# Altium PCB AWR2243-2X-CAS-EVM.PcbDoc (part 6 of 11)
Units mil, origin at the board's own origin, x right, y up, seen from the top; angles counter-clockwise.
Board outline 5118.11 x 3937.01 mil, 8 copper layers (Layer 1 - Top Layer, Layer 2 - GND, Layer 3 - Signal (Sensitive), Layer 4 - GND / Signal, Layer 5 - Signal, Layer 6 - PWR / Signal, Layer 7 - GND, Layer 8 - Bottom Layer), stack 54.8 mil thick; 629 components, 407 nets, 2243 pads, 3950 vias.
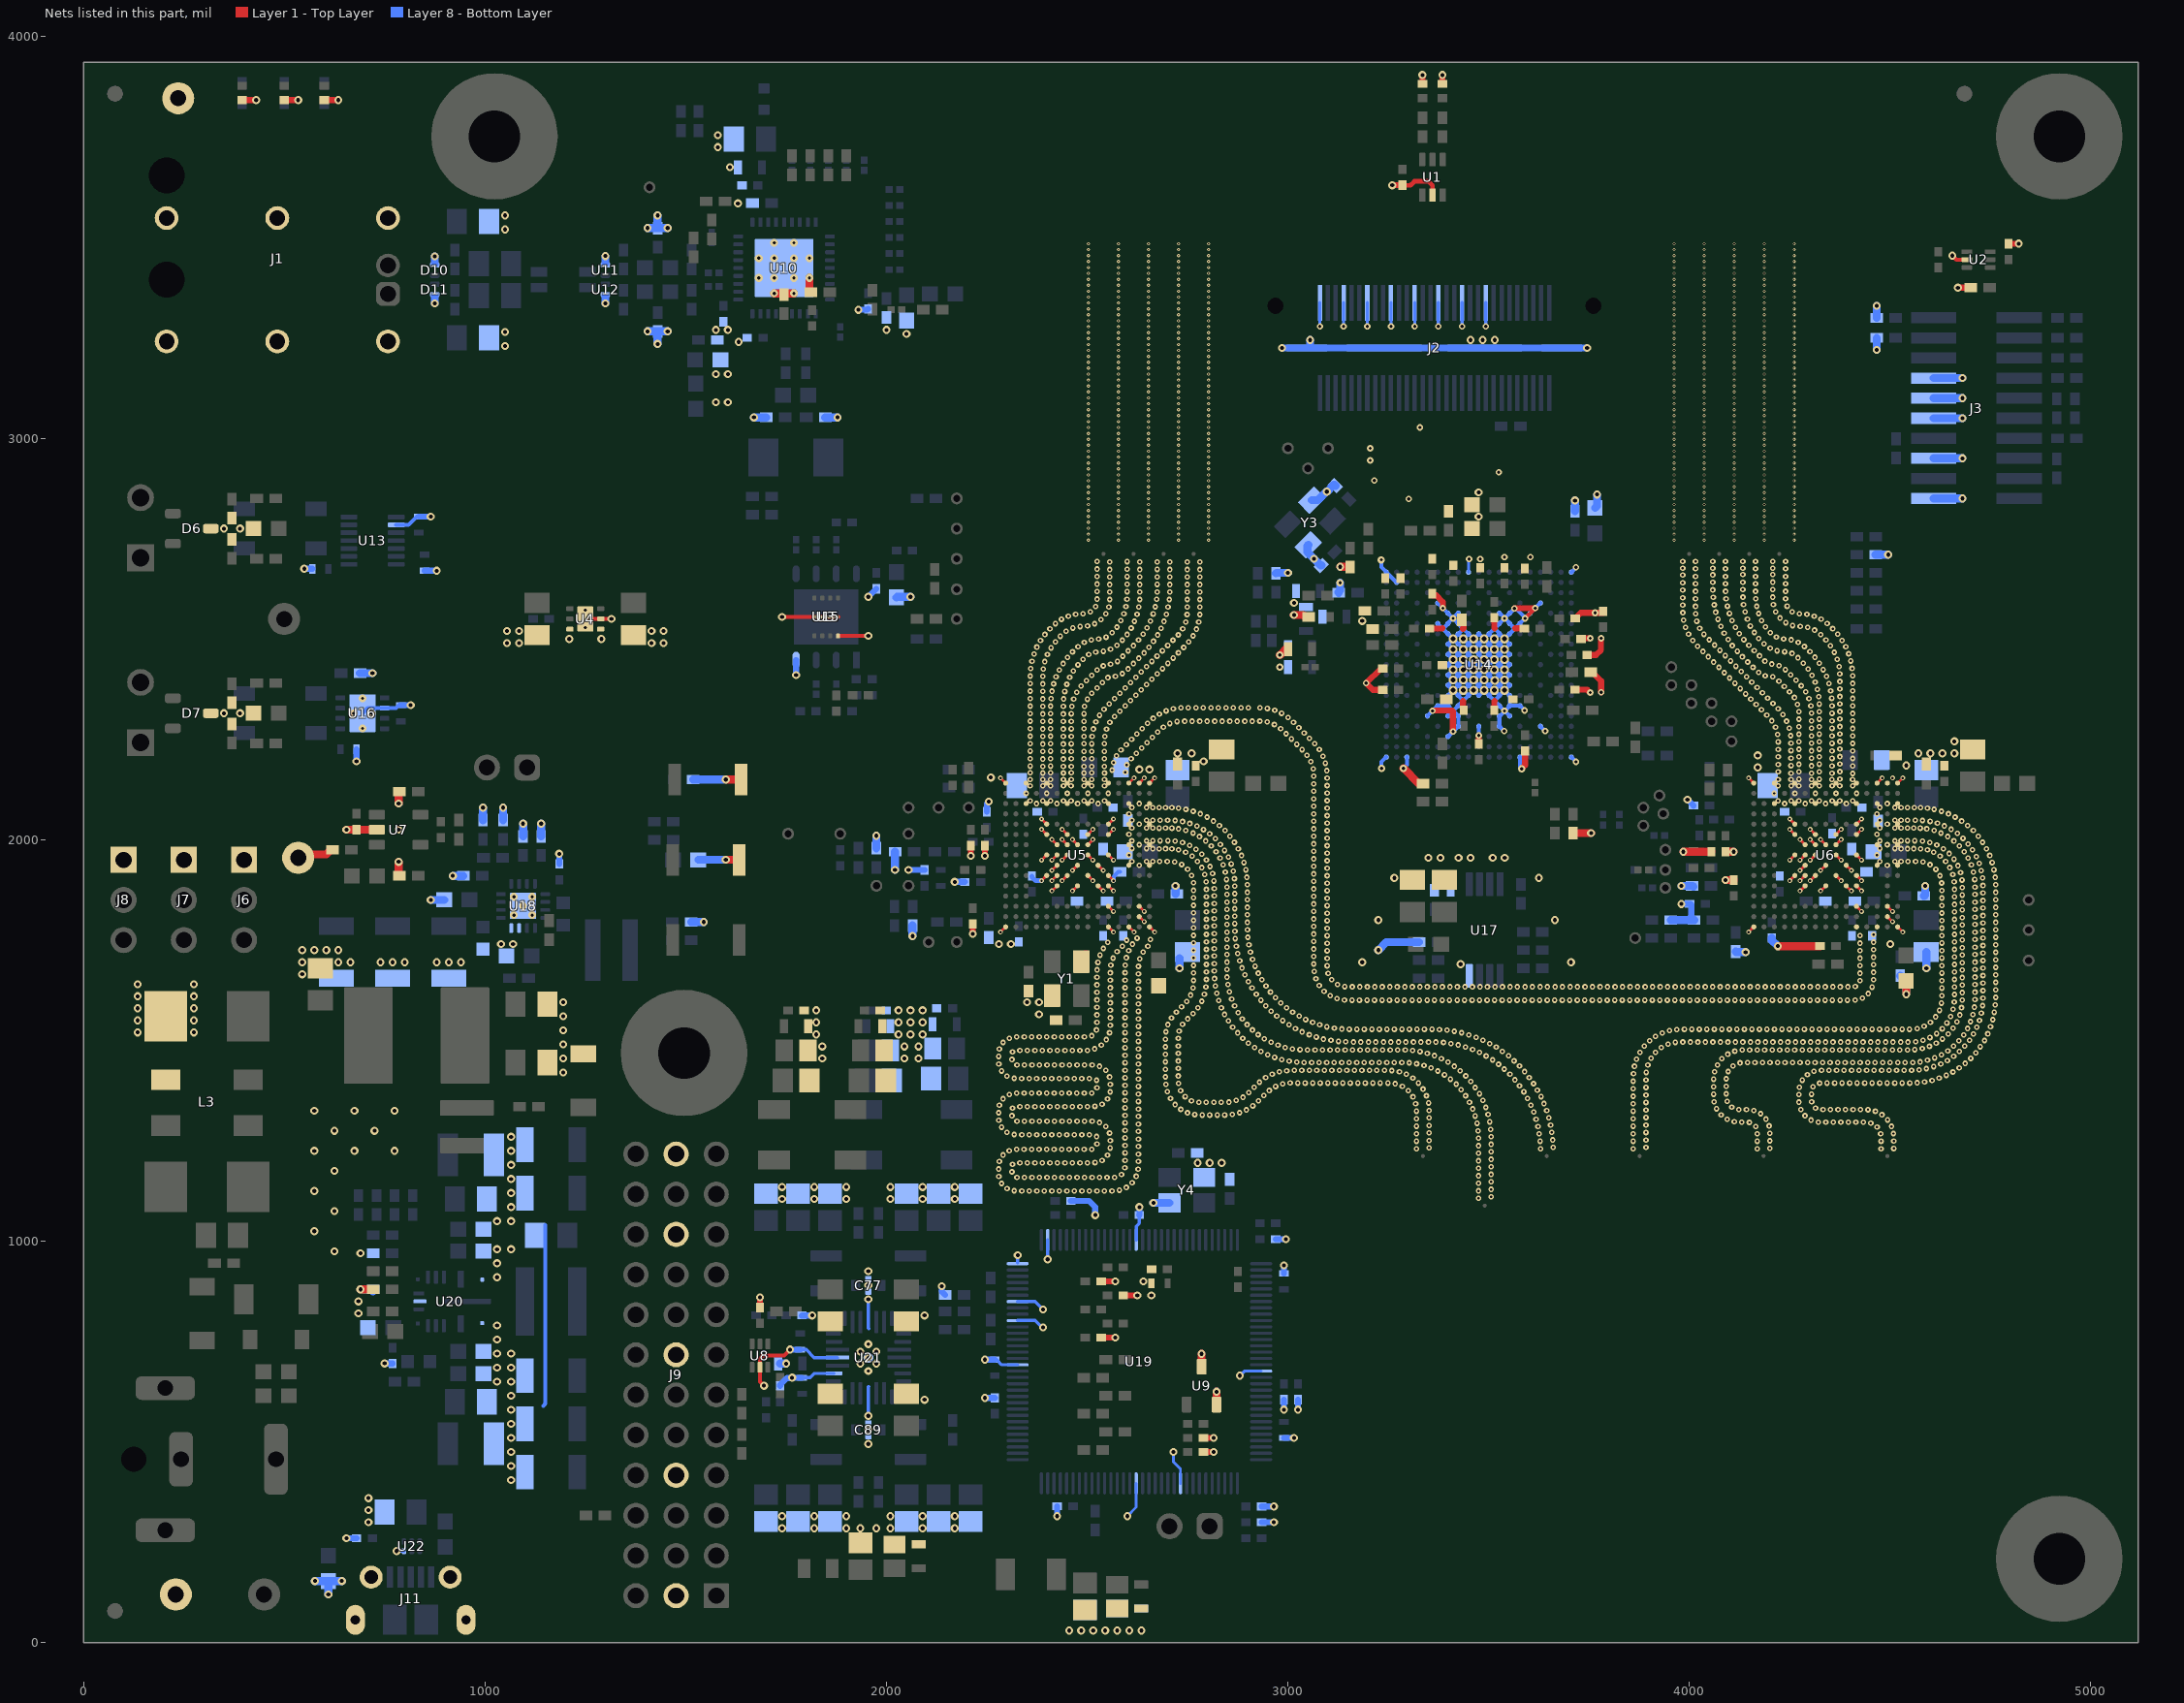
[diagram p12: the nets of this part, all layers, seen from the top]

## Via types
v1: diameter 13.78, hole 5.91, Layer 1 - Top Layer to Layer 2 - GND, tented top, 2104 vias
v2: diameter 20, hole 10, Layer 1 - Top Layer to Layer 8 - Bottom Layer, tented both sides, 831 vias
v3: diameter 7.87, hole 3.94, Layer 1 - Top Layer to Layer 2 - GND, tented top, 510 vias
v4: diameter 12, hole 6, Layer 1 - Top Layer to Layer 8 - Bottom Layer, tented both sides, 176 vias
v5: diameter 16, hole 8, Layer 1 - Top Layer to Layer 8 - Bottom Layer, tented both sides, 138 vias
v6: diameter 13.78, hole 5.91, Layer 1 - Top Layer to Layer 2 - GND, tented both sides, 88 vias
v7: diameter 18, hole 8, Layer 1 - Top Layer to Layer 8 - Bottom Layer, tented both sides, 41 vias
v8: diameter 22, hole 12, Layer 1 - Top Layer to Layer 8 - Bottom Layer, tented both sides, 36 vias
v9: diameter 19.68, hole 7.87, Layer 1 - Top Layer to Layer 8 - Bottom Layer, tented both sides, 26 vias

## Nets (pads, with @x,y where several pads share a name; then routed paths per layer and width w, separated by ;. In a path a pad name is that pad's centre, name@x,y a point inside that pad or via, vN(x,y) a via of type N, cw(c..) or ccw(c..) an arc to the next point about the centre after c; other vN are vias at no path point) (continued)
GND: C1.1 C2.1 C3.2 C4.1 C5.1 C6.1 C7.2 C8.1 C9.1 C10.1 C11.1 C12.1 C13.1 C14.1 C15.1 C16.2 C17.2 C18.2 C19.1 C20.1 C21.1 C22.1 C23.1 C24.1 C25.2 C26.1 C27.1 C28.1 C29.2 C30.2 C31.1 C32.1 C33.2 C34.1 C35.1 C36.1 C37.1 C38.2 C39.1 C40.2 C41.2 C42.1 C43.2 C44.2 C45.2 C46.2 C47.2 C48.1 C50.2 C51.2 C52.2 C53.2 C54.2 C55.1 C56.2 C57.2 C58.2 C59.2 C60.2 C62.2 C63.2 C64.2 C65.2 C66.2 C67.2 C68.2 C69.2 C70.2 C71.2 C72.2 C73.2 C74.2 C76.1 C77.2 C78.2 C79.2 C80.2 C82.2 C84.2 C86.2 C87.2 C89.2 C90.1 C91.1 C92.2 C93.2 C94.2 C95.2 C96.2 C97.2 C98.2 C99.1 C100.1 C104.2 C106.1 C107.1 C108.2 C109.2 C110.2 C111.1 C112.2 C113.2 C114.2 C115.2 C116.1 C117.2 C118.2 C119.2 C120.1 C121.2 C122.1 C123.2 C124.2 C125.2 C126.2 C127.2 C128.2 C129.2 C130.2 C131.2 C132.2 C133.2 C134.2 C135.2 C136.2 C137.2 C138.2 C139.2 C140.2 C141.2 C142.2 C143.2 C144.2 C145.2 C146.2 C147.2 C148.2 C149.2 C150.2 C151.2 C152.2 C153.1 C154.2 C155.2 C156.2 C157.2 C158.1 C159.2 C160.2 C161.2 C162.2 C163.2 C164.2 C165.2 C166.2 C168.2 C169.2 C170.2 C171.2 C172.2 C173.2 C174.2 C175.2 C176.2 C177.2 C178.2 C179.2 C180.2 C181.2 C183.2 C184.2 C185.2 C186.2 C187.2 C188.2 C189.2 C190.2 C191.2 C192.2 C193.2 C194.2 C195.1 C196.2 C197.2 C198.2 C199.2 C200.2 C201.2 C202.2 C203.2 C204.2 C205.1 C206.2 C207.2 C208.1 C209.2 C210.2 C211.1 C212.1 C213.1 C214.2 C215.1 C216.2 C218.2 C219.2 C220.2 C221.1 C222.1 C223.1 C224.2 C225.1 C226.2 C227.2 C228.2 C229.2 C230.2 C231.2 C232.2 C233.2 C234.2 C235.2 C236.2 C237.1 C238.1 C239.2 C240.2 C241.2 C242.2 C243.2 C244.2 D1.2 D2.2 D3.2 D4.2 D5.1 D6.3 D7.3 D10.2 D11.2 J1.S1 J1.S2 J1.S3 J1.S4 J1.S5 J1.S6 J2.18 J2.24 J2.30 J2.36 J2.42 J2.48 J2.54 J2.60 J2.MP1 J2.MP2 J2.MP3 J2.MP4 J3.8 J3.10 J3.12 J3.16 J3.20 J6.1 J7.1 J8.1 J9.2 J9.11 J9.20 J9.29 J9.35 J11.6 J11.9 J11.10 J11.11 L3.3 R12.2 R13.1 R14.2 R19.1 R22.1 R27.1 R28.1 R30.1 R39.1 R46.1 R50.1 R52.1 R57.1 R59.1 R65.1 R66.1 R67.1 R72.1 R96.1 R111.1 R114.1 R128.1 R136.1 R137.1 R147.1 R159.1 R160.1 R166.1 R167.1 R171.1 R174.1 R176.1 R179.1 R182.2 R185.1 R186.1 R188.1 R190.1 R191.1 R192.1 R194.1 R198.1 R200.1 R214.1 R217.1 R230.1 R232.1 R233.1 R239.2 R241.2 S1.2 S2.2 TP1.1 TP28.1 TP41.1 U1.2 U2.2 U3.4 U3.9 U4.3 U4.4 U4.5 U4.7@1250,2550 U5.A1 U5.A3 U5.A5 U5.A7 U5.A9 U5.A15 U5.B1 U5.B3 U5.B5 U5.B7 U5.B9 U5.B13 U5.B14 U5.C1 U5.C3 U5.C4 U5.C5 U5.C6 U5.C7 U5.C8 U5.C9 U5.C15 U5.E1 U5.E2 U5.E3 U5.E5 U5.E6 U5.E8 U5.E10 U5.E11 U5.E13 U5.E15 U5.F3 U5.F9 U5.F11 U5.G1 U5.G2 U5.G3 U5.G6 U5.G7 U5.G8 U5.G10 U5.H3 U5.H7 U5.H9 U5.H11 U5.J1 U5.J2 U5.J3 U5.J6 U5.J7 U5.J8 U5.J10 U5.K3 U5.K7 U5.K8 U5.K9 U5.K10 U5.K11 U5.L1 U5.L2 U5.L3 U5.L5 U5.L6 U5.L8 U5.L10 U5.M3 U5.N1 U5.N2 U5.N3 U5.R1 U5.R15 U6.A1 U6.A3 U6.A5 U6.A7 U6.A9 U6.A15 U6.B1 U6.B3 U6.B5 U6.B7 U6.B9 U6.B13 U6.B14 U6.C1 U6.C3 U6.C4 U6.C5 U6.C6 U6.C7 U6.C8 U6.C9 U6.C15 U6.E1 U6.E2 U6.E3 U6.E5 U6.E6 U6.E8 U6.E10 U6.E11 U6.E13 U6.E15 U6.F3 U6.F9 U6.F11 U6.G1 U6.G2 U6.G3 U6.G6 U6.G7 U6.G8 U6.G10 U6.H3 U6.H7 U6.H9 U6.H11 U6.J1 U6.J2 U6.J3 U6.J6 U6.J7 U6.J8 U6.J10 U6.K3 U6.K7 U6.K8 U6.K9 U6.K10 U6.K11 U6.L1 U6.L2 U6.L3 U6.L5 U6.L6 U6.L8 U6.L10 U6.M3 U6.N1 U6.N2 U6.N3 U6.R1 U6.R15 U7.2 U8.2 U9.2 U9.3 U10.37 U11.1 U12.1 U13.2 U14.A1 U14.A3 U14.A14 U14.A19 U14.C7 U14.D8 U14.D10 U14.D12 U14.D16 U14.E5 U14.E7 U14.E8 U14.E12 U14.E13 U14.F6 U14.F7 U14.F8 U14.F12 U14.F13 U14.F14 U14.G7 U14.G8 U14.G9 U14.G10 U14.G11 U14.G12 U14.G13 U14.H7 U14.H8 U14.H9 U14.H10 U14.H11 U14.H12 U14.H13 U14.J7 U14.J8 U14.J9 U14.J10 U14.J11 U14.J12 U14.J13 U14.K7 U14.K8 U14.K9 U14.K10 U14.K11 U14.K12 U14.K13 U14.L7 U14.L8 U14.L9 U14.L10 U14.L11 U14.L12 U14.L13 U14.M7 U14.M8 U14.M9 U14.M10 U14.M11 U14.M12 U14.M13 U14.N7 U14.N8 U14.N9 U14.N10 U14.N11 U14.N12 U14.N13 U14.P6 U14.P7 U14.P8 U14.P12 U14.P13 U14.P14 U14.R7 U14.R8 U14.R12 U14.R13 U14.R15 U14.T6 U14.T16 U14.V2 U14.W1 U14.W9 U14.W19 U15.4 U16.2 U16.9 U17.4 U18.7 U18.8 U18.17 U19.10 U19.17 U19.48 U19.55 U19.58 U19.64 U19.66 U19.80 U19.114 U20.1 U20.8 U20.15 U21.13 U21.19 U21.21 U22.3 Y1.2 Y1.4 Y3.2 Y3.4 Y4.2 Y4.4 | length 14094
  Layer 1 - Top Layer w7: v4(2284.05,1770.08) U5.R15@2296.85,1782.87 ; v4(2284.05,2153.94) U5.R1@2296.85,2141.14 ; v4(2386.42,1898.03) U5.L10@2399.21,1910.83 ; v4(2386.42,1949.21) U5.L8@2399.21,1962.01 ; v4(2386.42,2025.98) U5.L6@2399.21,2013.19 ; v4(2386.42,2051.57) U5.L5@2399.21,2038.78 ; v4(2412.01,1872.44) U5.K11@2424.8,1885.24 ; v4(2412.01,1898.03) U5.K10@2424.8,1910.83 ; v4(2412.01,1923.62) U5.K9@2424.8,1936.42 ; v4(2412.01,1949.21) U5.K8@2424.8,1962.01 ; v4(2412.01,2000.39) U5.K7@2424.8,1987.6 ; v4(2437.6,1898.03) U5.J10@2450.39,1910.83 ; v4(2437.6,1949.21) U5.J8@2450.39,1962.01 ; v4(2437.6,2000.39) U5.J7@2450.39,1987.6 ; v4(2437.6,2025.98) U5.J6@2450.39,2013.19 ; v4(2463.19,1872.44) U5.H11@2475.98,1885.24 ; v4(2463.19,1923.62) U5.H9@2475.98,1936.42 ; v4(2463.19,2000.39) U5.H7@2475.98,1987.6 ; U5.G10@2501.57,1910.83 v4(2514.37,1898.03) ; U5.G8@2501.57,1962.01 v4(2514.37,1949.21) ; U5.G7@2501.57,1987.6 v4(2514.37,2000.39) ; U5.G6@2501.57,2013.19 v4(2514.37,2025.98) ; U5.F11@2527.17,1885.24 v4(2539.96,1872.44) ; U5.F9@2527.17,1936.42 v4(2539.96,1923.62) ; U5.E15@2552.76,1782.87 v4(2565.55,1770.08) ; U5.E13@2552.76,1834.06 v4(2565.55,1821.26) ; U5.E11@2552.76,1885.24 v4(2565.55,1872.44) ; U5.E10@2552.76,1910.83 v4(2565.55,1898.03) ; U5.E8@2552.76,1962.01 v4(2565.55,1949.21) ; U5.E6@2552.76,2013.19 v4(2565.55,2025.98) ; U5.E5@2552.76,2038.78 v4(2565.55,2051.58) ; U5.C15@2603.94,1782.87 v4(2616.73,1770.08) ; U5.C1@2603.94,2141.14 v4(2616.73,2153.94) ; U5.B14@2629.53,1808.46 v4(2642.32,1795.67) ; U5.B13@2629.53,1834.06 v4(2642.32,1821.26) ; U5.B1@2629.53,2141.14 v4(2642.32,2153.94) ; U5.A15@2655.12,1782.87 v4(2667.91,1770.08) ; U5.A1@2655.12,2141.14 v4(2667.91,2153.94) ; v4(4147.44,1770.08) U6.R15@4160.24,1782.87 ; v4(4147.44,2153.94) U6.R1@4160.24,2141.14 ; v4(4249.8,1898.03) U6.L10@4262.6,1910.83 ; v4(4249.8,1949.21) U6.L8@4262.6,1962.01 ; v4(4249.8,2025.98) U6.L6@4262.6,2013.19 ; v4(4249.8,2051.57) U6.L5@4262.6,2038.78 ; v4(4275.39,1872.44) U6.K11@4288.19,1885.24 ; v4(4275.39,1898.03) U6.K10@4288.19,1910.83 ; v4(4275.39,1923.62) U6.K9@4288.19,1936.42 ; v4(4275.39,1949.21) U6.K8@4288.19,1962.01 ; v4(4275.39,2000.39) U6.K7@4288.19,1987.6 ; v4(4300.98,1898.03) U6.J10@4313.78,1910.83 ; v4(4300.98,1949.21) U6.J8@4313.78,1962.01 ; v4(4300.98,2000.39) U6.J7@4313.78,1987.6 ; v4(4300.98,2025.98) U6.J6@4313.78,2013.19 ; v4(4326.58,1872.44) U6.H11@4339.37,1885.24 ; v4(4326.58,1923.62) U6.H9@4339.37,1936.42 ; v4(4326.57,2000.39) U6.H7@4339.37,1987.6 ; U6.G10@4364.96,1910.83 v4(4377.76,1898.03) ; U6.G8@4364.96,1962.01 v4(4377.76,1949.21) ; U6.G7@4364.96,1987.6 v4(4377.76,2000.39) ; U6.G6@4364.96,2013.19 v4(4377.76,2025.98) ; U6.F11@4390.55,1885.24 v4(4403.35,1872.44) ; U6.F9@4390.55,1936.42 v4(4403.35,1923.62) ; U6.E13@4416.14,1834.06 v4(4428.94,1821.26) ; U6.E11@4416.14,1885.24 v4(4428.94,1872.44) ; U6.E10@4416.14,1910.83 v4(4428.94,1898.03) ; U6.E8@4416.14,1962.01 v4(4428.94,1949.21) ; U6.E6@4416.14,2013.19 v4(4428.94,2025.98) ; U6.E5@4416.14,2038.78 v4(4428.94,2051.58) ; U6.C1@4467.32,2141.14 v4(4480.12,2153.94) ; U6.B14@4492.91,1808.46 v4(4505.71,1795.67) ; U6.B13@4492.91,1834.06 v4(4505.71,1821.26) ; U6.A15@4518.5,1782.87 v4(4531.3,1770.08) ; U6.A1@4518.5,2141.14 v4(4531.3,2153.94)
  Layer 1 - Top Layer w10: U4.7@1250,2550 U4.5@1288.39,2550 v2(1315,2550) ; v2(1695,640) 1685,650 U8.2@1685,685.87 1685,708.24 1691.76,715 1745,715 v2(1760,730) ; v2(1740,2555) U3.9@1850,2555 U3.9@1880,2555 ; U3.4@1881,2507.76 v2(1955,2507.76) ; v5(3590.55,2551.3) v5(3616.14,2576.89) ; v2(4655,3455) 4665,3445 U2.2@4690.87,3445
  Layer 1 - Top Layer w12: C1.1@3285.31,3630 3305,3630 3315,3640 3350,3640 3360,3630 U1.2@3360,3605.71
  Layer 1 - Top Layer w15: D3.2@395,3842.28 v2(430,3842.28) ; D4.2@500,3842.28 v2(535,3842.28) ; D5.1@600,3842.28 v2(635,3842.28) ; C82.2@1685,834.69 v2(1685,860) ; v2(2210,1960) C50.2@2210,1985.31 ; v2(2215,1765.63) C57.2@2215,1790.31 ; v2(2245,1960) C51.2@2245,1985.31 ; R72.1@2534.68,760 v2(2570,760) ; R65.1@2534.68,900 v2(2570,900) ; R67.1@2589.68,865 v2(2625,865) ; C91.1@2789.68,475 v2(2815,475) ; C90.1@2789.68,510 v2(2815,510) ; C28.1@3236.15,2426.35 3235.89,2426.61 3231.61,2426.61 v5(3195,2390) 3211.62,2373.38 C32.1@3236.2,2373.38 ; v2(3260,3630.32) C1.1@3285,3630.32 ; D1.2@3335,3882.72 v2(3335,3905) ; C22.1@3352.79,2525.71 3383.7,2525.71 3384.63,2526.63 3384.9,2526.63 ; C15.1@3359.76,2612.77 3359.76,2610.8 3362.1,2608.46 3369.54,2608.46 3385.83,2592.17 v5(3385.83,2576.89) ; v5@3361.16,2321.91 3408.37,2321.91 3410.49,2319.79 v5@3410.49,2269.8 ; D2.2@3385,3882.72 v2(3385,3905) ; C37.1@3435.7,2322.69 3435.89,2322.88 3435.89,2345.46 3436.08,2345.65 ; 3436.08,2524.78 3436.08,2526.91 3437.09,2527.91 C18.2@3437.09,2553.1 ; C42.1@3475.39,2238.95 v5(3475.39,2260) ; C36.1@3512.69,2322.69 3513.7,2323.7 3513.7,2344.64 3514.71,2345.65 ; C19.1@3513.96,2553.1 3513.96,2527.65 3514.71,2526.91 3514.71,2526.63 ; v5(3564.03,2575.96) 3564.31,2575.96 3565.23,2576.89 v5(3616.14,2576.89) ; 3565.89,2526.63 3566.08,2526.44 3587.84,2526.44 C23.1@3588.7,2525.58 ; v7(3581.96,2176.35) 3581.96,2177.16 3590.54,2185.74 C39.1@3590.54,2221.2 ; C31.1@3714.77,2373.58 3745.47,2373.58 3752.55,2366.51 v5(3752.82,2366.51) ; C21.1@3715.37,2551.05 3729.32,2565 v7(3765,2565) C20.1@3785,2565 ; C24.1@3729.84,2499.87 3731.56,2501.59 3752.63,2501.59 v5(3752.82,2501.78) ; C26.1@3745.35,2460.17 3767.17,2460.17 3779.81,2472.81 3779.81,2501.81 v5(3780,2502) ; C29.2@3758.54,2417.01 3780,2395.55 v5(3780,2367) ; v2(4668.74,3375) R12.2@4700.75,3375 ; C2.1@4795.16,3484.84 v2(4820.16,3484.84)
  Layer 1 - Top Layer w20: TP28.1@535,1955 543.31,1963.31 605,1963.31 616.69,1975 R52.1@620.63,1975 ; v2(655,2025) U7.2@730.87,2025 ; v2(690,880) R66.1@716.38,880 ; v2(785,1945) 785,1916.38 R57.1@790,1911.38 ; v2(785,2090) 785,2118.62 C47.2@786.38,2120 ; v2(1600,1950) S2.2@1632.68,1950 ; v2(1600,2150) S1.2@1637.68,2150 ; v9(1720.39,3361.01) v9(1769.61,3361.01) ; v9(1807.99,3399.39) 1807.99,3365.81 1809.8,3364 R13.1@1811.38,3364 ; Y1.2@2485.61,1696.44 2485.61,1704.31 Y1.2@2496.28,1714.98 ; U9.3@2785,687.52 v2(2785,719.49) ; U9.2@2822.4,593.04 v2(2822.4,625) ; v7(2980,2460) C25.2@3000,2480 ; v2(3015,2560) 3038,2560 3043,2555 R28.1@3051.38,2555 ; v2(3130,2680) 3154.38,2680 R22.1@3155,2679.38 ; v7(3287.84,2177.97) 3325.81,2140 R46.1@3336.38,2140 ; R50.1@3710,2016.38 v2(3755,2016.38) ; C29.2@3754.61,2417.01 C29.2@3758.54,2417.01 ; v2(3985,1970) 4054.84,1970 4055,1970.16 C52.2@4055,1970.31 ; v2(4090,1899.37) C56.2@4109.84,1899.37 ; C53.2@4090,1970.31 4090,1970.16 4090.16,1970 v2(4110,1970) ; v2(4220,1735) R59.1@4325.32,1735 ; v2(4540,1615) C58.2@4540,1648.5
  Layer 8 - Bottom Layer w7: v2(2600,315) 2622.13,337.13 U19.17@2622.12,396.85 ; v2(2715,475) 2715,450 2732.36,432.64 U19.10@2732.36,396.85
  Layer 8 - Bottom Layer w8: v2(780,228.19) U22.3@798.31,228.19 ; C213.1@1785,730 1800,730 1820,710 U21.21@1878.23,710 ; C219.2@1790,660 1810,660 1820.63,670.63 U21.19@1869.37,670.63 ; v2(1955,565) 1955,637 1956,638 ; v2(1955,855) 1955,783 1956,782 ; C218.2@2270,705 2274.5,705 2287.31,692.19 2326.79,692.19 U19.48@2326.85,692.13 ; U19.55@2326.85,802.36 2370.39,802.36 2387.76,785 v2(2390,785) ; U19.58@2326.85,849.61 2370.39,849.61 v2(2390,830) ; U19.64@2326.85,946 v2(2326.85,965) ; v2(2401.65,955) U19.66@2401.65,1003.15 ; U19.80@2622.12,1003.15 2622.13,1037.13 2629.68,1044.68 C205.1@2629.68,1065 ; v2(2880,665) 2891.38,676.38 U19.114@2933.15,676.38 ; v5(3079.57,3279) J2.60@3079.57,3337.8 ; v5(3138.62,3279) J2.54@3138.62,3337.8 ; v5(3197.68,3279) J2.48@3197.68,3337.8 ; v5(3256.73,3279) J2.42@3256.73,3337.8 ; v5(3315.79,3279) J2.36@3315.79,3337.8 ; v5(3374.84,3279) J2.30@3374.84,3337.8 ; v5(3433.9,3279) J2.24@3433.9,3337.8 ; U14.W9@3449.8,2666.46 3449.8,2698.07 v5(3451.08,2699.35) ; v5(3492.95,3279) J2.18@3492.95,3337.8
  Layer 8 - Bottom Layer w10: U16.9@695,2315 707.8,2327.8 U16.2@750.12,2327.8 778.3,2327.8 785.5,2335 C129.2@790,2335 ; U13.2@779.06,2784.37 809.37,2784.37 830,2805 C117.2@835,2805 ; 1145,590 1150,595 1150,1040 ; v4(2565.55,1898.03) 2565.93,1898.41 2565.93,1908.49 2577.44,1920 C155.2@2581.38,1920 ; v7(3232.61,2697.32) 3232.61,2678.92 U14.V2@3270.67,2640.87 ; v7(3233,2178) 3233,2193.75 U14.A1@3245.08,2205.83 ; v7(3287.84,2177.97) 3296.26,2186.4 U14.A3@3296.26,2205.83 ; U14.E5@3347.44,2308.19 U14.F6@3372.93,2333.67 ; U14.F6@3373.03,2333.78 U14.F7@3398.62,2333.78 ; U14.P6@3373.03,2538.5 3384.9,2526.63 ; U14.T6@3373.03,2589.69 v5@3410.49,2552.23 ; U14.C7@3398.62,2257.01 U14.D8@3424.21,2282.6 U14.E8@3424.21,2308.19 3413.49,2318.91 3411.64,2318.91 3410.49,2320.06 ; U14.E7@3398.62,2308.19 3410.49,2320.06 ; U14.R8@3424.21,2564.09 3423.4,2564.09 3421.9,2562.59 3420.86,2562.59 v5@3410.49,2552.23 ; U14.G10@3474.58,2359.37 U14.G10@3475.39,2359.37 ; U14.N10@3474.58,2512.91 U14.N10@3475.39,2512.91 ; v5(3475.39,2260) U14.D10@3475.39,2282.6 ; v8@3489,2372.17 v8@3488.59,2371.76 ; U14.M11@3501.8,2487.32 U14.M11@3501.39,2487.73 ; U14.D12@3526.57,2282.6 U14.E12@3526.57,2308.19 3527.39,2308.19 3528.89,2309.69 3529.93,2309.69 v5@3540.3,2320.06 ; U14.R12@3526.57,2564.09 3527.39,2564.09 3528.89,2562.59 3529.93,2562.59 v5@3540.3,2552.23 ; U14.D12@3526.68,2282.49 v5(3538.44,2270.73) ; U14.G12@3527.39,2359.37 U14.G12@3526.57,2359.37 ; U14.E13@3552.17,2308.19 v5@3540.3,2320.06 ; U14.A14@3577.75,2205.83 3577.76,2180.56 v7(3581.96,2176.35) ; U14.F14@3577.75,2333.78 U14.F13@3552.17,2333.78 ; U14.F14@3577.86,2333.67 v5(3589.63,2321.91) ; U14.R15@3603.24,2563.99 v5@3591.48,2552.23 ; U14.R15@3603.35,2564.09 v5(3616.14,2576.89) ; v5@3617.07,2577.82 U14.T16@3628.83,2589.58 ; U14.D16@3628.94,2282.6 v5(3640.81,2270.73) ; U14.A19@3705.71,2205.83 v5(3717.58,2193.96) ; U14.W19@3705.71,2666.46 v5(3717.58,2678.33) ; 3384.9,2526.63 3386.05,2527.78 3387.9,2527.78 U14.P7@3398.62,2538.5 3398.62,2539.32 3400.12,2540.82 3400.12,2541.86 v5@3410.49,2552.23 ; 3384.9,2526.63 U14.N7@3398.62,2512.91 v8(3411.42,2500.12) ; U14.F7@3398.62,2333.78 3409.34,2323.06 3409.34,2321.21 3410.49,2320.06 ; U14.F7@3398.62,2333.78 U14.G7@3398.62,2359.37 v8(3411.42,2372.17) ; 3410.49,2320.06 3436.08,2345.65 ; v5@3410.49,2552.23 U14.P8@3424.21,2538.5 3436.08,2524.78 ; v8(3411.42,2372.17) U14.G8@3424.21,2359.37 ; v8(3411.42,2372.17) U14.H7@3398.62,2384.96 v8(3411.42,2397.76) ; v8(3411.42,2372.17) U14.H8@3424.21,2384.96 ; v8(3411.42,2397.76) U14.J7@3398.62,2410.55 v8(3411.42,2423.35) ; v8(3411.42,2397.76) U14.J8@3424.21,2410.55 ; v8(3411.42,2397.76) U14.H8@3424.21,2384.96 ; v8(3411.42,2423.35) U14.K7@3398.62,2436.14 v8(3411.42,2448.94) ; v8(3411.42,2423.35) U14.K8@3424.21,2436.14 ; v8(3411.42,2423.35) U14.J8@3424.21,2410.55 ; v8(3411.42,2448.94) U14.L7@3398.62,2461.73 v8(3411.42,2474.53) ; v8(3411.42,2448.94) U14.L8@3424.21,2461.73 ; v8(3411.42,2448.94) U14.K8@3424.21,2436.14 ; v8(3411.42,2474.53) U14.M7@3398.62,2487.32 v8(3411.42,2500.12) ; v8(3411.42,2474.53) U14.L8@3424.21,2461.73 ; v8(3411.42,2500.12) U14.M8@3424.21,2487.32 v8(3437.01,2474.53) ; v8(3411.42,2500.12) U14.N8@3424.21,2512.91 ; U14.G8@3424.21,2359.37 v8(3437.01,2372.17) ; U14.G8@3424.21,2359.37 3424.21,2358.56 3436.08,2346.69 3436.08,2345.65 ; U14.H8@3424.21,2384.96 v8(3437.01,2372.17) ; U14.H8@3424.21,2384.96 v8(3437.01,2397.76) ; U14.J8@3424.21,2410.55 v8(3437.01,2397.76) ; U14.J8@3424.21,2410.55 v8(3437.01,2423.35) ; U14.K8@3424.21,2436.14 v8(3437.01,2448.94) ; U14.K8@3424.21,2436.14 v8(3437.01,2423.35) ; U14.L8@3424.21,2461.73 v8(3437.01,2448.94) ; U14.L8@3424.21,2461.73 v8(3437.01,2474.53) ; U14.N8@3424.21,2512.91 3436.08,2524.78 ; U14.N8@3424.21,2512.91 v8(3437.01,2500.12) ; 3436.08,2345.65 U14.G9@3449.8,2359.37 ; 3436.08,2524.78 U14.N9@3449.8,2512.91 ; v8(3437.01,2372.17) U14.G9@3449.8,2359.37 ; v8(3437.01,2372.17) U14.H9@3449.8,2384.96 ; v8(3437.01,2397.76) U14.H9@3449.8,2384.96 ; v8(3437.01,2397.76) U14.J9@3449.8,2410.55 ; v8(3437.01,2423.35) U14.J9@3449.8,2410.55 ; v8(3437.01,2423.35) U14.K9@3449.8,2436.14 ; v8(3437.01,2448.94) U14.K9@3449.8,2436.14 ; v8(3437.01,2448.94) U14.L9@3449.8,2461.73 ; v8(3437.01,2474.53) U14.L9@3449.8,2461.73 ; v8(3437.01,2474.53) U14.M9@3449.8,2487.32 ; v8(3437.01,2500.12) U14.M9@3449.8,2487.32 ; v8(3437.01,2500.12) U14.N9@3449.8,2512.91 ; U14.G9@3449.8,2359.37 v8(3462.6,2372.17) ; U14.H9@3449.8,2384.96 v8(3462.6,2372.17) ; U14.H9@3449.8,2384.96 v8(3462.6,2397.76) ; U14.J9@3449.8,2410.55 v8(3462.6,2397.76) ; U14.J9@3449.8,2410.55 v8(3462.6,2423.35) ; U14.K9@3449.8,2436.14 v8(3462.6,2448.94) ; U14.K9@3449.8,2436.14 v8(3462.6,2423.35) ; U14.L9@3449.8,2461.73 v8(3462.6,2448.94) ; U14.L9@3449.8,2461.73 v8(3462.6,2474.53) ; U14.M9@3449.8,2487.32 v8(3462.6,2500.12) ; U14.M9@3449.8,2487.32 v8(3462.6,2474.53) ; U14.N9@3449.8,2512.91 v8(3462.6,2500.12) ; v8(3462.6,2372.17) U14.G10@3475.39,2359.37 ; v8(3462.6,2372.17) U14.H10@3475.39,2384.96 ; v8(3462.6,2397.76) U14.J10@3475.39,2410.55 ; v8(3462.6,2397.76) U14.H10@3475.39,2384.96 ; v8(3462.6,2423.35) U14.J10@3475.39,2410.55 ; v8(3462.6,2423.35) U14.K10@3475.39,2436.14 ; v8(3462.6,2448.94) U14.K10@3475.39,2436.14 ; v8(3462.6,2474.53) U14.M10@3475.39,2487.32 ; v8(3462.6,2474.53) U14.L10@3475.39,2461.73 ; v8(3462.6,2500.12) U14.N10@3475.39,2512.91 ; v8(3462.6,2500.12) U14.M10@3475.39,2487.32 ; U14.G10@3475.39,2359.37 3476.21,2359.37 v8@3488.59,2371.76 ; U14.H10@3475.39,2384.96 v8(3488.19,2372.17) ; U14.H10@3475.39,2384.96 v8(3488.19,2397.76) ; U14.J10@3475.39,2410.55 v8(3488.19,2397.76) ; U14.J10@3475.39,2410.55 v8(3488.19,2423.35) ; U14.K10@3475.39,2436.14 v8(3488.19,2448.94) ; U14.K10@3475.39,2436.14 v8(3488.19,2423.35) ; U14.L10@3475.39,2461.73 v8(3488.19,2448.94) ; U14.L10@3475.39,2461.73 v8(3488.19,2474.53) ; U14.M10@3475.39,2487.32 v8(3488.19,2474.53) ; U14.M10@3475.39,2487.32 v8(3488.19,2500.12) v8@3488.59,2500.52 ; U14.N10@3475.39,2512.91 3476.21,2512.91 v8@3488.59,2500.52 ; v8(3488.19,2372.17) U14.H11@3500.98,2384.96 ; v8(3488.19,2372.17) v8@3488.59,2371.76 ; v8(3488.19,2397.76) U14.H11@3500.98,2384.96 ; v8(3488.19,2397.76) U14.J11@3500.98,2410.55 ; v8(3488.19,2423.35) U14.J11@3500.98,2410.55 ; v8(3488.19,2423.35) U14.K11@3500.98,2436.14 ; v8(3488.19,2448.94) U14.K11@3500.98,2436.14 ; v8(3488.19,2448.94) U14.L11@3500.98,2461.73 ; v8(3488.19,2474.53) U14.M11@3500.98,2487.32 ; v8(3488.19,2474.53) U14.L11@3500.98,2461.73 ; v8@3488.59,2371.76 U14.G11@3500.98,2359.37 ; v8@3488.59,2500.52 U14.N11@3500.98,2512.91 ; v8@3488.59,2500.52 U14.M11@3501.39,2487.73 ; U14.G11@3500.98,2359.37 3514.71,2345.65 ; U14.G11@3500.98,2359.37 v8(3513.78,2372.17) ; U14.H11@3500.98,2384.96 v8(3513.78,2372.17) ; U14.H11@3500.98,2384.96 3501.8,2384.96 3513.67,2396.83 v8(3514.71,2396.83) ; U14.J11@3500.98,2410.55 v8(3514.71,2396.83) ; U14.J11@3500.98,2410.55 v8(3513.78,2423.35) ; U14.K11@3500.98,2436.14 v8(3513.78,2448.94) ; U14.K11@3500.98,2436.14 v8(3513.78,2423.35) ; U14.L11@3500.98,2461.73 v8(3513.78,2448.94) ; U14.L11@3500.98,2461.73 v8(3513.78,2474.53) ; U14.M11@3500.98,2487.32 U14.M11@3501.39,2487.73 ; U14.M11@3500.98,2487.32 v8(3513.78,2474.53) ; U14.N11@3500.98,2512.91 3514.71,2526.63 ; U14.N11@3500.98,2512.91 v8(3513.78,2500.12) ; U14.M11@3501.39,2487.73 v8(3513.78,2500.12) ; v8(3513.78,2372.17) U14.G12@3526.57,2359.37 ; v8(3513.78,2372.17) U14.H12@3526.57,2384.96 ; v8(3513.78,2423.35) U14.J12@3526.57,2410.55 ; v8(3513.78,2423.35) U14.J12@3526.57,2410.55 ; v8(3513.78,2423.35) U14.K12@3526.57,2436.14 ; v8(3513.78,2448.94) U14.K12@3526.57,2436.14 ; v8(3513.78,2448.94) U14.L12@3526.57,2461.73 v8(3539.37,2448.94) ; v8(3513.78,2474.53) U14.M12@3526.57,2487.32 ; v8(3513.78,2474.53) U14.L12@3526.57,2461.73 v8(3539.37,2474.53) ; v8(3513.78,2500.12) U14.N12@3526.57,2512.91 ; v8(3513.78,2500.12) U14.M12@3526.57,2487.32 ; 3514.71,2345.65 3514.71,2346.69 3526.57,2358.56 U14.G12@3526.57,2359.37 ; 3514.71,2345.65 v5@3540.3,2320.06 ; v8(3514.71,2396.83) U14.H12@3526.57,2384.96 ; v8(3514.71,2396.83) 3514.71,2397.87 3526.57,2409.74 U14.J12@3526.57,2410.55 ; 3514.71,2526.63 3525.07,2516.27 3525.07,2515.23 3526.57,2513.73 U14.N12@3526.57,2512.91 ; 3514.71,2526.63 v5@3540.3,2552.23 ; U14.G12@3526.57,2359.37 v8(3539.37,2372.17) ; U14.H12@3526.57,2384.96 v8(3539.37,2372.17) ; U14.H12@3526.57,2384.96 v8(3539.37,2397.76) ; U14.J12@3526.57,2410.55 v8(3539.37,2423.35) ; U14.J12@3526.57,2410.55 v8(3539.37,2397.76) ; U14.K12@3526.57,2436.14 v8(3539.37,2448.94) ; U14.K12@3526.57,2436.14 v8(3539.37,2423.35) ; U14.M12@3526.57,2487.32 v8(3539.37,2474.53) ; U14.M12@3526.57,2487.32 v8(3539.37,2500.12) ; U14.N12@3526.57,2512.91 v8(3539.37,2500.12) ; v8(3539.37,2372.17) 3552.17,2359.37 U14.F13@3552.17,2333.78 ; v8(3539.37,2372.17) 3552.17,2384.96 v8(3539.37,2397.76) ; v8(3539.37,2397.76) 3552.17,2410.55 v8(3539.37,2423.35) ; v8(3539.37,2423.35) 3552.17,2436.14 v8(3539.37,2448.94) ; v8(3539.37,2448.94) 3552.17,2461.73 v8(3539.37,2474.53) ; v8(3539.37,2474.53) 3552.17,2487.32 v8(3539.37,2500.12) ; v8(3539.37,2500.12) 3565.89,2526.63 ; v5@3540.3,2320.06 3550.67,2330.43 3550.67,2331.47 3552.17,2332.97 U14.F13@3552.17,2333.78 ; v5@3540.3,2552.23 3550.67,2541.86 3550.67,2540.82 3552.17,2539.32 3552.17,2538.5 3562.89,2527.78 3564.74,2527.78 3565.89,2526.63 ; v5@3540.3,2552.23 v5(3564.03,2575.96) 3565.66,2575.96 3568.66,2572.96 3570.74,2572.96 v5@3591.48,2552.23 ; 3565.89,2526.63 v5@3591.48,2552.23
  Layer 8 - Bottom Layer w12: C157.2@2362,1909.69 2362,1907.72 2371.69,1898.03 v4(2386.42,1898.03)
  Layer 8 - Bottom Layer w15: v2(550,2675) C121.2@570,2675 ; v2(655,260) R232.1@680.31,260 ; v2(680,2195) C130.2@680,2225 ; v2(750.16,695.47) C215.1@769.84,695.47 ; C129.2@790,2335 v2(815,2335) ; C117.2@835,2805 v2(865,2805) ; C119.2@850,2670 v2(880,2670) ; C153.1@1185,1939.68 v2(1185,1965) ; C223.1@1735,639.68 1735,641.65 1752.39,659.04 1764.04,659.04 v2(1765,660) C219.2@1790,660 ; v2(1760,730) C213.1@1785,730 ; v2(1775,2410) U15.4@1775,2447.66 ; C211.1@1789.68,814.33 1790.02,814.67 1814.67,814.67 v2(1815,815) ; v2(1930,3320) 1951.68,3320 C106.1@1954,3322.32 ; v2(1955,2605) 1955,2605.32 C122.1@1975,2625.32 ; v2(2055,1924.68) R179.1@2095,1924.68 ; v2(2138,888) 2138,874.38 R241.2@2146.38,866 ; v2(2170,1895) R185.1@2195.31,1895 ; v2(2245,609.68) C225.1@2270,609.68 ; v2(2245,705) C218.2@2270,705 ; R160.1@2250,2069.68 2250,2090 v2(2255,2095) ; v2(2425.32,315) C237.1@2425.31,340 ; C204.2@2459.68,1100 2505,1100 2520,1085 v2(2520,1065) ; C205.1@2629.68,1065 2630,1065.32 v2(2630,1085) ; R230.1@2934.68,300 v2(2965,300) ; C238.1@2934.68,339.25 v2(2965,339.25) ; C208.1@2969.68,1005 v2(2995,1005) ; C228.2@2990,510 v2(3015,510) ; v2(2990,580.32) C222.1@2990,605.32 ; C210.2@2990,920 v2(2990,940) ; v2(3025,580.32) C221.1@3025,605.32 ; v2(3980,1840) R190.1@4000.31,1840 4002.28,1840 4004.63,1837.66 4004.63,1804.31 4008.94,1800 R191.1@4011.38,1800 ; v2(3985,1970) R176.1@4010.31,1970 ; v2(3995,2100) 3995,2100.32 R159.1@4010.31,2085 ; R191.1@4008.35,1804.31 R191.1@4012.66,1800
  Layer 8 - Bottom Layer w17: v2(2985,3225) J2.MP4@3047.48,3225 J2.MP3@3240,3225 J2.MP2@3490,3225 J2.MP1@3682.52,3225 v2(3745,3225)
  Layer 8 - Bottom Layer w20: v2(576.5,153.5) R233.1@610,153.5 ; v2(610,120) R233.1@610,153.5 ; v2(643.5,153.5) R233.1@610,153.5 ; R147.1@688.62,2415 v2(720,2415) ; v2(690,880) 716.38,880 R217.1@721.38,875 ; v2(865,1850) C162.2@898.5,1850 ; v2(875,3336) D11.2@875,3354 ; D10.2@875,3435 v2(875,3453) ; v2(920,1910) R182.2@946.38,1910 ; C145.2@995,2048.62 v2(995,2080) ; C144.2@1045,2048.62 v2(1045,2080) ; R167.1@1095,2008.62 v2(1095,2040) ; R166.1@1140,2008.62 v2(1140,2040) ; v2(1300,3336) U12.1@1300,3354 ; U11.1@1300,3436 v2(1300,3454) ; v2(1405,3266.38) C108.2@1430,3266.38 ; v2(1405,3523.62) C100.1@1430,3523.62 ; v2(1430,3235) C108.2@1430,3266.38 ; v2(1430,3555) C100.1@1430,3523.62 ; v2(1455,3266.38) C108.2@1430,3266.38 ; v2(1455,3523.62) C100.1@1430,3523.62 ; R194.1@1513.62,1795 v2(1545,1795) ; C137.2@1518.62,2150 v2(1600,2150) ; C152.2@1531.5,1950 v2(1600,1950) ; v2(1670,3052) C114.2@1700.38,3052 ; C84.2@1735,695 v2(1750,695) ; C113.2@1847.62,3052 v2(1878,3052) ; R171.1@1975,1978.62 v2(1975,2010) ; v2(2021.38,1925) R174.1@2021.38,1970 ; C120.1@2025,2603.5 2026.5,2605 v2(2060,2605) ; v2(2065,1760) R188.1@2065,1786.38 ; v2(2665,1095.51) Y4.4@2704.8,1095.51 ; C161.2@2720,1865 v2(2720,1885) ; v2(2730,1680) C169.2@2730,1705 ; R137.1@2970,2663.62 2971.38,2665 v2(3000,2665) ; Y3.2@3050.82,2734.32 3048.3,2731.79 3048.3,2716.7 v2(3065,2700) 3081.7,2683.3 C118.2@3083.3,2683.3 ; J2.MP4@3055,3227 v2(3055,3245) ; Y3.4@3059.17,2845.68 3074.26,2845.68 3095.59,2867 v2(3097,2867) 3113.72,2883.72 3116.28,2883.72 C115.2@3118.3,2881.7 ; C124.2@3126.38,2615 3125,2616.38 3130,2621.38 v7(3130,2640) ; v2(3225,1725) 3245,1745 R198.1@3326.38,1745 ; R128.1@3715,2818.62 v2(3715,2845) ; C116.1@3765,2826.5 3770,2831.5 v2(3770,2860) ; R192.1@3953.62,1800 R191.1@4008.94,1800 ; v2(3980,1885) R186.1@4006.38,1885 4008.5,1885 R186.1@4010.31,1883.19 ; R191.1@4011.38,1800 R191.1@4012.66,1800 ; C181.2@4115,1721.38 4116.38,1720 v2(4140,1720) ; C175.2@4205,1755.31 4205,1750 v2(4220,1735) ; R136.1@4463.62,2710 v2(4495,2710) ; v2(4466.38,3220) R114.1@4466.38,3250 ; R111.1@4466.38,3300 v2(4466.38,3330) ; R200.1@4525,1661.38 4540,1646.38 v2(4540,1615) ; C160.2@4583.62,1860 4585.43,1860 4587.24,1861.81 v2(4587.24,1885) ; v2(4590,1680) C168.2@4590,1720 ; J3.20@4608.5,2850 v2(4680,2850) ; J3.16@4608.5,2950 v2(4680,2950) ; J3.12@4608.5,3050 v2(4680,3050) ; J3.10@4608.5,3100 v2(4680,3100) ; J3.8@4608.5,3150 v2(4680,3150)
